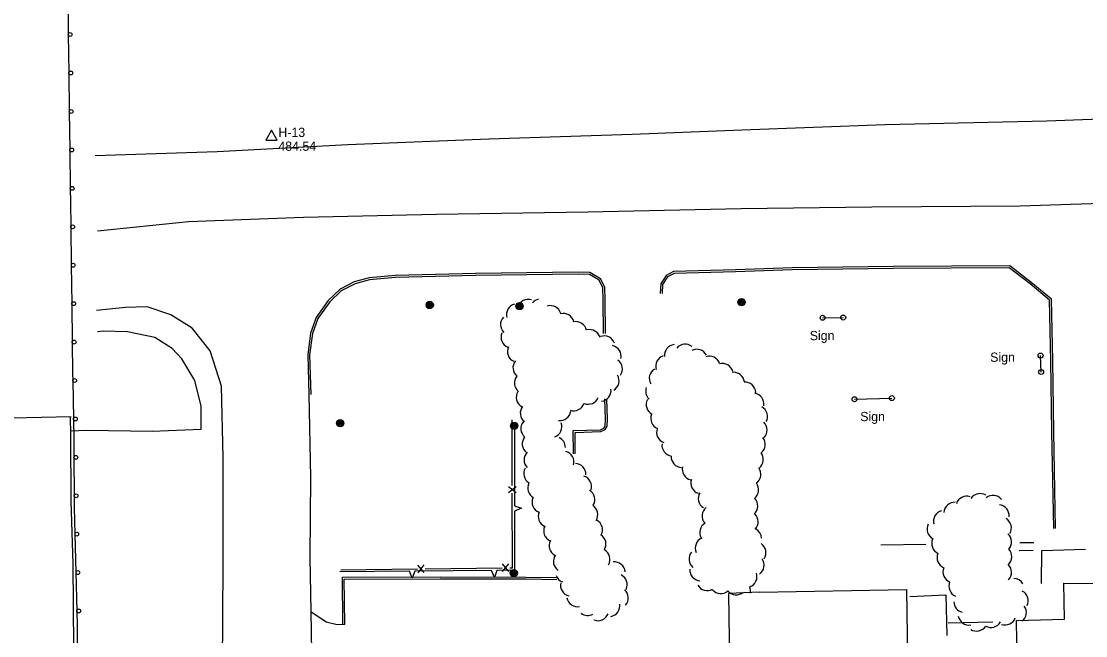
# Model space of a CAD drawing. Extents: x 2402803 to 2427059, y 6985292 to 6997652.
# Drawn here: x 2420163 to 2420717, y 6991117 to 6991436 of the extents above; entities that cross this region are included whole.
import ezdxf

# ---------------------------------------------------------------- set-up
doc = ezdxf.new("R2010")
doc.units = 0
for name, color, linetype in [('p_control ground ctrl', 7, 'Continuous'), ('p_drainage riprap', 7, 'Continuous'), ('p_dtm retaining wall', 7, 'Continuous'), ('p_dtm sidewalk', 7, 'Continuous'), ('p_road - paved curb', 7, 'Continuous'), ('p_road bridge end', 7, 'Continuous'), ('p_road guard rails', 7, 'Continuous'), ('p_structure building', 7, 'Continuous'), ('p_structure fence', 7, 'Continuous'), ('p_structure sign', 7, 'Continuous'), ('p_utility manhole', 7, 'Continuous'), ('p_veg woods', 7, 'Continuous'), ('V7 LEVEL 31', 7, 'Continuous')]:
    doc.layers.add(name, color=color, linetype=linetype)

msp = doc.modelspace()

# ---------------------------------------------------------------- linework, layer by layer
at = {"layer": 'p_control ground ctrl'}
for p, q in [((2420293.39, 6991379.8), (2420290.39, 6991374.6)), ((2420296.39, 6991374.6), (2420293.39, 6991379.8)), ((2420290.39, 6991374.6), (2420296.39, 6991374.6)), ((2420293.39, 6991376.32), (2420293.39, 6991376.36))]:
    msp.add_line(p, q, dxfattribs=at)
at = {"layer": 'p_drainage riprap'}
msp.add_lwpolyline([(2420188.75, 6991223.56), (2420197.37, 6991223.93), (2420231.27, 6991223.42), (2420256.78, 6991224.38), (2420256.88, 6991236.46), (2420253.48, 6991249.67), (2420246.81, 6991261.05), (2420241.74, 6991266.43), (2420232.77, 6991272.03), (2420218.44, 6991275.04), (2420205.84, 6991275.44), (2420202.94, 6991275.08)], dxfattribs=at)
at = {"layer": 'p_dtm retaining wall'}
for p, q in [((2420419.73, 6991224.64), (2420419.77, 6991184.64)), ((2420365.07, 6991150.56), (2420328.99, 6991150.23)), ((2420407.84, 6991150.95), (2420367.84, 6991150.59))]:
    msp.add_line(p, q, dxfattribs=at)
for points in [[(2420419.77, 6991181.87), (2420419.8, 6991151.06), (2420410.61, 6991150.98)], [(2420419.77, 6991184.64), (2420423.4, 6991183.32), (2420419.77, 6991181.87)], [(2420367.84, 6991150.59), (2420366.56, 6991146.94), (2420365.07, 6991150.56)], [(2420410.61, 6991150.98), (2420409.32, 6991147.33), (2420407.84, 6991150.95)]]:
    msp.add_lwpolyline(points, dxfattribs=at)
at = {"layer": 'p_dtm sidewalk'}
for points in [[(2420610.17, 6991164.38), (2420633.71, 6991164.61)], [(2420682.46, 6991165.53), (2420689.75, 6991165.46)], [(2420689.48, 6991161.36), (2420682.22, 6991161.26)]]:
    msp.add_lwpolyline(points, dxfattribs=at)
at = {"layer": 'p_road - paved curb'}
for points in [[(2420537.91, 6991379.97), (2420612.53, 6991382.78), (2420696.6, 6991384.67), (2420770.92, 6991387.44), (2420845.86, 6991390.84), (2420917.37, 6991392.83), (2420997.57, 6991394.08), (2420997.57, 6991393.72), (2420997.6, 6991393.73), (2421067.29, 6991394.52), (2421067.28, 6991394.7), (2421131.11, 6991395.5), (2421178, 6991395.2), (2421235.72, 6991391.05), (2421235.75, 6991391.06), (2421283.59, 6991388.28), (2421348.8, 6991385.13), (2421416.71, 6991381.03), (2421481.1, 6991376.79), (2421539.62, 6991373.35), (2421610.6, 6991369.27), (2421736.95, 6991360.69)], [(2420201.7, 6991366.66), (2420265.19, 6991368.71), (2420333.03, 6991372.32), (2420406.34, 6991375.28), (2420480.9, 6991377.84), (2420537.91, 6991379.97)], [(2420537.56, 6991339.15), (2420605.53, 6991339.92), (2420682.64, 6991340.56), (2420719.59, 6991341.7), (2420763.71, 6991342.01), (2420820.41, 6991342.42), (2420865.24, 6991342.82), (2420923.39, 6991343.45), (2420985.83, 6991344.24), (2421050.86, 6991345.19), (2421109.83, 6991346.09), (2421162.12, 6991346.4), (2421221.5, 6991348.02), (2421294.97, 6991348.99), (2421362.75, 6991349.74), (2421418.85, 6991349.45), (2421472.47, 6991347.66), (2421531.42, 6991344.68), (2421598.78, 6991338.55), (2421682.34, 6991329.62), (2421735.83, 6991323.83)], [(2420202.91, 6991327.6), (2420250.27, 6991332.43), (2420310.07, 6991334.7), (2420379.18, 6991336.26), (2420457.95, 6991337.33), (2420537.56, 6991339.15)], [(2420534.63, 6991307.24), (2420502.49, 6991306.41), (2420498.69, 6991304.3), (2420495.78, 6991300.04), (2420495.51, 6991295.03)], [(2420701.15, 6991172.76), (2420700.23, 6991223.05), (2420699.69, 6991259.88), (2420698.99, 6991291.96), (2420688.46, 6991300.74), (2420677.27, 6991309.24), (2420616.88, 6991308.97), (2420564.1, 6991308.2), (2420534.63, 6991307.24)], [(2420700.15, 6991172.74), (2420699.23, 6991223.03), (2420698.69, 6991259.86), (2420698, 6991291.48), (2420687.84, 6991299.96), (2420676.94, 6991308.24), (2420616.89, 6991307.97), (2420564.12, 6991307.2), (2420534.66, 6991306.24)], [(2420467.05, 6991274.13), (2420466.82, 6991291.72), (2420466.64, 6991298.21), (2420464.51, 6991302.61), (2420458.96, 6991305.79), (2420452.81, 6991305.97), (2420399.38, 6991305.33), (2420357.88, 6991304.26), (2420344.17, 6991303.11), (2420336.44, 6991300.93), (2420329.02, 6991297.23), (2420322.92, 6991291.29), (2420316.57, 6991282.45), (2420313.67, 6991274.4), (2420312.21, 6991263.14), (2420312.81, 6991242.44)], [(2420466.05, 6991274.12), (2420465.82, 6991291.7), (2420465.65, 6991297.97), (2420463.74, 6991301.9), (2420458.68, 6991304.8), (2420452.8, 6991304.97), (2420399.4, 6991304.33), (2420357.93, 6991303.26), (2420344.35, 6991302.12), (2420336.8, 6991299.99), (2420329.61, 6991296.4), (2420323.68, 6991290.64), (2420317.46, 6991281.98), (2420314.65, 6991274.16), (2420313.21, 6991263.09), (2420313.81, 6991242.47)], [(2420534.66, 6991306.24), (2420502.76, 6991305.42), (2420499.38, 6991303.54), (2420496.76, 6991299.71), (2420496.51, 6991294.98)], [(2420268.05, 6990812.58), (2420267.36, 6990914.7), (2420267.14, 6990990.7), (2420267.65, 6991074.59), (2420268.22, 6991153.57), (2420268.31, 6991209.72), (2420267.36, 6991246.78), (2420261.46, 6991265.07), (2420252.08, 6991276.94), (2420241.11, 6991283.85), (2420228.73, 6991288.02), (2420217.48, 6991287.61), (2420202.41, 6991286.08)], [(2420312.81, 6991242.44), (2420313.72, 6991199.56), (2420313.28, 6991157.91), (2420313.77, 6991129.63), (2420314.43, 6991097.94), (2420313.94, 6991040.68), (2420314.18, 6990973.56), (2420316.82, 6990901.67), (2420316.45, 6990875.81), (2420314.28, 6990808.5)], [(2420450.35, 6991211.59), (2420450.21, 6991223.72), (2420464.47, 6991224.12), (2420466.25, 6991225), (2420466.95, 6991226.21), (2420467.06, 6991229.66), (2420466.76, 6991240.24)], [(2420451.35, 6991211.6), (2420451.22, 6991222.75), (2420464.72, 6991223.13), (2420466.96, 6991224.24), (2420467.94, 6991225.93), (2420468.06, 6991229.66), (2420467.76, 6991240.27)], [(2420188.66, 6991230.87), (2420188.78, 6991221.47), (2420189.06, 6991186.95), (2420190.05, 6991154.59), (2420190.47, 6991110.85), (2420190.34, 6991074.6), (2420191.43, 6991034.43), (2420191.94, 6990989.78), (2420192.4, 6990949.14), (2420193.29, 6990889.37), (2420194.31, 6990850.07), (2420195.61, 6990815.83)], [(2420330.49, 6991122.99), (2420330.23, 6991147.48), (2420381.01, 6991147.65), (2420425.72, 6991147.57), (2420441.83, 6991147.3)], [(2420331.49, 6991123), (2420331.24, 6991146.48), (2420381.01, 6991146.65), (2420425.71, 6991146.57), (2420441.81, 6991146.3)], [(2420313.77, 6991129.63), (2420321.77, 6991124.28), (2420327.53, 6991122.87), (2420331.49, 6991123)]]:
    msp.add_lwpolyline(points, dxfattribs=at)
at = {"layer": 'p_road bridge end'}
msp.add_lwpolyline([(2420142.67, 6991229.93), (2420189.16, 6991231.03)], dxfattribs=at)
at = {"layer": 'p_road guard rails'}
for p, q in [((2420187.69, 6991429.53), (2420187.95, 6991409.54)), ((2420187.95, 6991409.54), (2420188.2, 6991389.55)), ((2420188.2, 6991389.55), (2420188.46, 6991369.56)), ((2420188.46, 6991369.56), (2420188.71, 6991349.57)), ((2420188.96, 6991329.59), (2420189.22, 6991309.62)), ((2420189.22, 6991309.62), (2420189.47, 6991289.65)), ((2420189.47, 6991289.65), (2420189.72, 6991269.67)), ((2420190, 6991249.7), (2420190.37, 6991229.74)), ((2420190.62, 6991209.77), (2420190.75, 6991189.79)), ((2420191.13, 6991169.83), (2420191.63, 6991149.87)), ((2420191.63, 6991149.87), (2420192.13, 6991129.9))]:
    msp.add_line(p, q, dxfattribs=at)
for points in [[(2420187.39, 6991449.52), (2420187.64, 6991433.7), (2420187.69, 6991429.53)], [(2420188.71, 6991349.57), (2420188.8, 6991342.5), (2420188.96, 6991329.59)], [(2420189.72, 6991269.67), (2420189.93, 6991253.33), (2420190, 6991249.7)], [(2420190.37, 6991229.74), (2420190.56, 6991219.16), (2420190.62, 6991209.77)], [(2420190.75, 6991189.79), (2420190.79, 6991183.67), (2420190.79, 6991183.67), (2420191.13, 6991169.83)], [(2420192.13, 6991129.9), (2420192.31, 6991122.56), (2420192.38, 6991109.93)]]:
    msp.add_lwpolyline(points, dxfattribs=at)
for centre in [(2420188.69, 6991429.54), (2420188.95, 6991409.55), (2420189.2, 6991389.56), (2420189.46, 6991369.57), (2420189.71, 6991349.59), (2420189.96, 6991329.61), (2420190.22, 6991309.63), (2420190.47, 6991289.66), (2420190.72, 6991269.69), (2420191, 6991249.72), (2420191.36, 6991229.75), (2420191.62, 6991209.77), (2420191.75, 6991189.8), (2420192.13, 6991169.85), (2420192.63, 6991149.89), (2420193.13, 6991129.93)]:
    msp.add_circle(centre, 1, dxfattribs=at)
at = {"layer": 'p_structure building'}
for points in [[(2420547.24, 6991139.71), (2420623.55, 6991141.1), (2420624.45, 6991081.15), (2420622.78, 6991077.95), (2420624, 6990982.45), (2420543.65, 6990981.57)], [(2420547.24, 6991139.71), (2420531.09, 6991139.08), (2420531.82, 6991079.68), (2420534.3, 6991076.31), (2420535.55, 6990981.42), (2420543.65, 6990981.57)]]:
    msp.add_lwpolyline(points, dxfattribs=at)
msp.add_lwpolyline([(2420731.66, 6991144.13), (2420732.78, 6991084.89), (2420706.31, 6991084.53), (2420705.58, 6991103.02), (2420681.16, 6991103.41), (2420680.76, 6991125.02), (2420705.77, 6991125.62), (2420705.48, 6991144.3)], close=True, dxfattribs=at)
at = {"layer": 'p_structure fence'}
for p, q in [((2420418.57, 6991195.13), (2420418.51, 6991229.24)), ((2420420.54, 6991191.33), (2420416.54, 6991194.53)), ((2420420.54, 6991194.53), (2420416.54, 6991191.33)), ((2420329.37, 6991151.28), (2420369.37, 6991151.79)), ((2420372.79, 6991149.86), (2420369.54, 6991153.82)), ((2420369.59, 6991149.82), (2420372.74, 6991153.86)), ((2420373.36, 6991151.84), (2420413.36, 6991152.34)), ((2420416.78, 6991150.42), (2420413.53, 6991154.38)), ((2420413.59, 6991150.38), (2420416.73, 6991154.42)), ((2420645.22, 6991123.8), (2420668.54, 6991124.32))]:
    msp.add_line(p, q, dxfattribs=at)
for points in [[(2420417.36, 6991152.39), (2420418.64, 6991152.41), (2420418.57, 6991191.13)], [(2420693.89, 6991144.22), (2420693.91, 6991161.39), (2420716.73, 6991162.08)], [(2420625.27, 6991137.51), (2420644.05, 6991138.28), (2420644.58, 6991117.15)]]:
    msp.add_lwpolyline(points, dxfattribs=at)
at = {"layer": 'p_structure sign'}
for p, q in [((2420579.98, 6991282.3), (2420590.69, 6991282.46)), ((2420693.62, 6991254.12), (2420693.3, 6991262.64)), ((2420596.56, 6991239.99), (2420615.97, 6991240.55))]:
    msp.add_line(p, q, dxfattribs=at)
for centre in [(2420579.99, 6991282.31), (2420590.7, 6991282.47), (2420693.29, 6991262.65), (2420693.61, 6991254.13), (2420596.57, 6991240), (2420615.98, 6991240.56)]:
    msp.add_circle(centre, 1.3, dxfattribs=at)
at = {"layer": 'p_utility manhole'}
for centre, radius in [((2420375.65, 6991288.98), 1.9), ((2420375.65, 6991288.98), 1.44), ((2420422.35, 6991288.34), 1.9), ((2420537.76, 6991290.46), 1.9), ((2420537.76, 6991290.46), 1.44), ((2420537.76, 6991290.46), 0.973), ((2420537.76, 6991290.46), 0.539), ((2420537.76, 6991290.46), 0.192), ((2420375.65, 6991288.98), 0.973), ((2420375.65, 6991288.98), 0.539), ((2420375.65, 6991288.98), 0.192), ((2420422.35, 6991288.34), 1.44), ((2420422.35, 6991288.34), 0.973), ((2420422.35, 6991288.34), 0.539), ((2420422.35, 6991288.34), 0.192), ((2420329.11, 6991227.51), 1.9), ((2420329.11, 6991227.51), 1.44), ((2420329.11, 6991227.51), 0.973), ((2420329.11, 6991227.51), 0.539), ((2420329.11, 6991227.51), 0.192), ((2420419.59, 6991226.2), 1.9), ((2420419.59, 6991226.2), 1.44), ((2420419.59, 6991226.2), 0.973), ((2420419.59, 6991226.2), 0.539), ((2420419.59, 6991226.2), 0.192), ((2420419.35, 6991149.62), 1.9), ((2420419.35, 6991149.62), 1.44), ((2420419.35, 6991149.62), 0.973), ((2420419.35, 6991149.62), 0.539), ((2420419.35, 6991149.62), 0.192)]:
    msp.add_circle(centre, radius, dxfattribs=at)
at = {"layer": 'p_veg woods'}
for centre, start, end in [((2420426.89, 6991286.26), 72.6391, 162.6391), ((2420433.43, 6991286.49), 102.7854, 139.6304), ((2420421.27, 6991284.03), 106.0384, 196.0384), ((2420438.36, 6991283.01), 16.0056, 106.0056), ((2420445.06, 6991278.97), 13.6071, 103.6071), ((2420418.13, 6991278.87), 137.087, 227.087), ((2420451.7, 6991274.68), 12.1855, 102.1855), ((2420418.41, 6991272.24), 157.2085, 247.2085), ((2420458.8, 6991270.53), 15.4224, 105.4224), ((2420466.46, 6991267.25), 20.1155, 110.1155), ((2420469.57, 6991262.32), 347.4773, 77.4773), ((2420503.36, 6991262.76), 96.1094, 186.1094), ((2420508.48, 6991263), 50.3468, 140.3468), ((2420421.7, 6991264.84), 155.2266, 245.2266), ((2420498.83, 6991257.14), 107.6723, 197.6723), ((2420514.54, 6991260.29), 27.0343, 117.0343), ((2420521.06, 6991256.72), 18.4095, 108.4095), ((2420424.59, 6991256.37), 141.2633, 231.2633), ((2420470.2, 6991255.72), 324.9075, 54.9075), ((2420527.83, 6991252.88), 15.3912, 105.3912), ((2420425.33, 6991248.47), 141.8837, 231.8837), ((2420468.47, 6991249.53), 300.7372, 30.7372), ((2420495.48, 6991250.78), 119.6892, 209.6892), ((2420533.7, 6991248.34), 6.8855, 96.8855), ((2420493.6, 6991244.15), 159.6591, 226.4065), ((2420539.53, 6991243.24), 3.2234, 93.2234), ((2420426.32, 6991241), 148.5038, 238.5038), ((2420458.03, 6991243.03), 248.3487, 338.3487), ((2420464.32, 6991244.56), 276.9615, 6.9615), ((2420543.84, 6991237.47), 351.5054, 81.5054), ((2420428.41, 6991232.79), 141.8918, 231.8918), ((2420450.52, 6991239.63), 251.9819, 341.9819), ((2420493.9, 6991237.24), 152.2995, 242.2995), ((2420545.65, 6991231), 331.8721, 61.8721), ((2420443.43, 6991234.6), 261.8644, 351.8644), ((2420496.27, 6991230), 157.7552, 247.7552), ((2420428.68, 6991224.69), 140.1283, 230.1283), ((2420438.72, 6991225.7), 290.6379, 20.6379), ((2420499.28, 6991222.79), 160.4248, 250.4248), ((2420545.45, 6991224.01), 316.0673, 46.0673), ((2420429.42, 6991216.8), 141.2151, 231.2151), ((2420440.58, 6991214.92), 0.0574, 64.3785), ((2420544.55, 6991216.58), 308.5442, 38.5442), ((2420445.03, 6991207.33), 345.8517, 75.8517), ((2420502.09, 6991216.1), 171.9705, 261.9705), ((2420430.35, 6991208.45), 135.5437, 225.5437), ((2420506.81, 6991210.19), 178.0557, 268.0557), ((2420543.5, 6991208.73), 307.353, 37.353), ((2420430.19, 6991201.36), 149.4148, 239.4148), ((2420451.19, 6991200.97), 357.6482, 87.6482), ((2420512.66, 6991203.63), 166.8002, 256.8002), ((2420542.19, 6991200.94), 305.859, 35.859), ((2420432.26, 6991193.88), 152.8708, 242.8708), ((2420454.16, 6991194.64), 342.3795, 72.3795), ((2420517.09, 6991196.47), 160.9516, 250.9516), ((2420541.07, 6991192.91), 307.4241, 37.4241), ((2420455.89, 6991187.76), 329.131, 59.131), ((2420520.95, 6991188.45), 148.4879, 238.4879), ((2420661.83, 6991185.31), 57.1952, 147.1952), ((2420434.54, 6991186.55), 157.5855, 247.5855), ((2420457.41, 6991180.01), 327.6299, 57.6299), ((2420540.6, 6991184.58), 312.3875, 42.3875), ((2420648.69, 6991180.8), 86.9326, 176.9326), ((2420654.94, 6991183.95), 71.9895, 161.9895), ((2420668.63, 6991184.36), 39.4845, 129.4845), ((2420671.31, 6991179.48), 353.8867, 83.8867), ((2420437.72, 6991179.08), 155.8564, 245.8564), ((2420522.93, 6991179.22), 128.6124, 218.6124), ((2420540.82, 6991176.27), 316.7953, 46.7953), ((2420643.3, 6991176.57), 105.4451, 195.4451), ((2420440.57, 6991171.52), 154.7283, 244.7283), ((2420459.87, 6991172.18), 331.4837, 61.4837), ((2420521.72, 6991170.72), 120.132, 210.132), ((2420639.93, 6991172.47), 153.274, 243.274), ((2420672.49, 6991173.12), 329.0798, 59.0798), ((2420461.67, 6991164.65), 328.2546, 58.2546), ((2420542.54, 6991167.55), 2.785, 59.8134), ((2420672.58, 6991165.82), 318.2331, 48.2331), ((2420443.4, 6991163.86), 152.4345, 242.4345), ((2420519.39, 6991162.56), 113.1444, 203.1444), ((2420544.87, 6991160.31), 325.0821, 55.0821), ((2420642.35, 6991165.02), 155.8099, 245.8099), ((2420445.66, 6991155.72), 145.7477, 235.7477), ((2420463.75, 6991156.75), 330.7147, 60.7147), ((2420516.14, 6991156.98), 140.7228, 230.7228), ((2420645.12, 6991157.64), 157.4783, 247.4783), ((2420672.69, 6991158.18), 313.2469, 43.2469), ((2420471.65, 6991149.8), 5.4529, 95.4529), ((2420516.56, 6991151.28), 176.4557, 266.4557), ((2420543.93, 6991153.78), 304.8034, 34.8034), ((2420648.18, 6991150.27), 157.751, 247.751), ((2420672.58, 6991150), 315.9254, 45.9254), ((2420446.66, 6991150.3), 200.5421, 248.9992), ((2420472.74, 6991143.59), 334.5308, 64.5308), ((2420540.21, 6991147.76), 289.5858, 19.5858), ((2420679.18, 6991141.23), 29.608, 87.9447), ((2420449.34, 6991143.23), 165.872, 255.872), ((2420473.26, 6991136.69), 318.5453, 48.5453), ((2420519.98, 6991146.13), 209.4406, 299.4406), ((2420527, 6991144.61), 220.7034, 310.7034), ((2420536.79, 6991140.56), 346.66, 19.5858), ((2420651.27, 6991142.9), 157.751, 247.751), ((2420452.6, 6991137.74), 190.232, 280.232), ((2420534.98, 6991144.01), 220.7034, 310.7034), ((2420681.25, 6991135.23), 333.7427, 63.7427), ((2420468.94, 6991132.67), 278.6717, 8.6717), ((2420653.87, 6991134.78), 180.1875, 256.6794), ((2420680.32, 6991129.09), 306.5439, 36.5439), ((2420457.87, 6991133.25), 231.9403, 298.4165), ((2420463.09, 6991130.52), 249.1965, 339.1965), ((2420656.08, 6991128.27), 189.9152, 279.9152), ((2420667.58, 6991127.02), 240.3523, 330.3523), ((2420674.84, 6991128.28), 250.6611, 340.6611), ((2420660.03, 6991125.1), 237.4521, 327.4521)]:
    msp.add_arc(centre, 5.65, start, end, dxfattribs=at)

# ---------------------------------------------------------------- texts
at = {"layer": 'p_control ground ctrl'}
msp.add_text('  H-13', height=4.8, dxfattribs=at).set_placement((2420293.39, 6991376.32))
at = {"layer": 'p_structure sign'}
for p in [(2420573.29, 6991270.69), (2420667.12, 6991259.44), (2420599.54, 6991228.6)]:
    msp.add_text('Sign', height=4.8, dxfattribs=at).set_placement(p)
at = {"layer": 'V7 LEVEL 31'}
msp.add_text('  484.54', height=4.8, dxfattribs=at).set_placement((2420293.39, 6991369.12))

doc.saveas('drawing.dxf')
